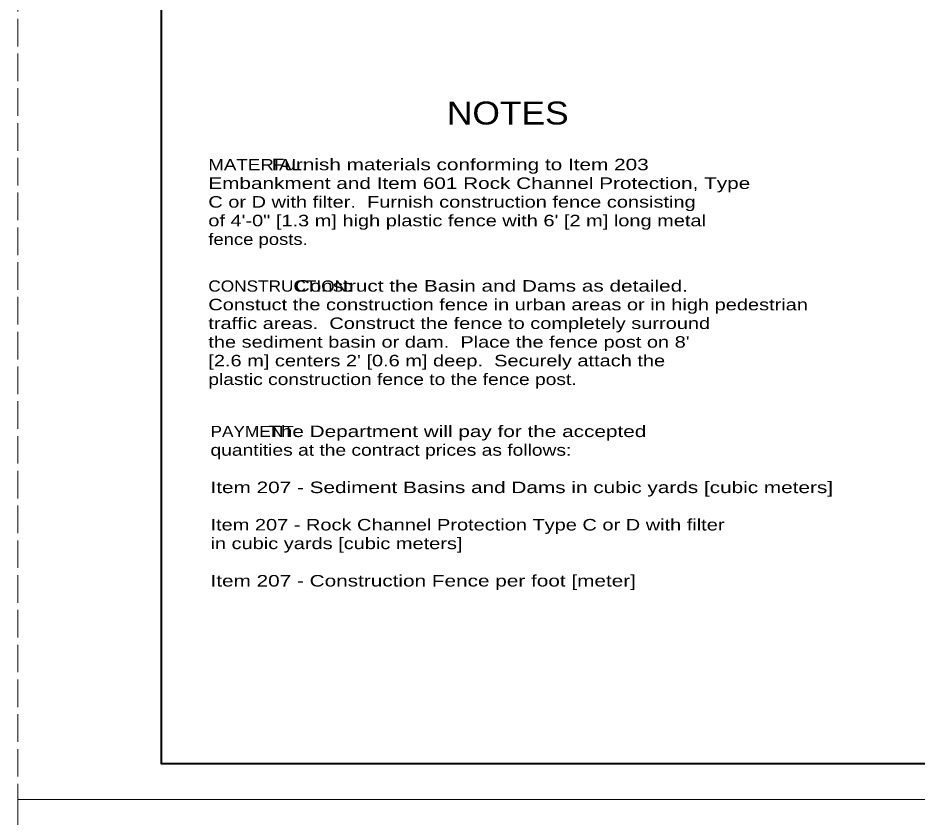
# Model space of a CAD drawing. Extents: x 1043.1 to 1101.1, y 672.4 to 716.4.
# Drawn here: x 1043.14 to 1055.66, y 694.15 to 705.27 of the extents above; entities that cross this region are included whole.
import ezdxf
from ezdxf.enums import TextEntityAlignment as Align

# ---------------------------------------------------------------- set-up
doc = ezdxf.new("R2010")
doc.units = 0
doc.header["$LTSCALE"] = 0.064
doc.linetypes.add('LONG_DASHED', pattern=[7.5, 6, -1.5])
doc.layers.add('1', color=7, linetype='Continuous', lineweight=13)

msp = doc.modelspace()

# ---------------------------------------------------------------- linework, layer by layer
at = {"layer": '1', "linetype": 'LONG_DASHED'}
for points in [[(1043.14425, 694.39508), (1077.14425, 694.39508), (1077.14425, 716.39508), (1043.14425, 716.39508)], [(1043.14425, 672.39508), (1077.14425, 672.39508), (1077.14425, 694.39508), (1043.14425, 694.39508)]]:
    msp.add_lwpolyline(points, close=True, dxfattribs=at)
at = {"layer": '1', "lineweight": 25}
msp.add_lwpolyline([(1076.64425, 694.89508), (1045.14425, 694.89508), (1045.14425, 715.89508)], dxfattribs=at)
at = {"layer": '1', "lineweight": 40}
msp.add_lwpolyline([(1045.14425, 715.89508), (1076.64425, 715.89508), (1076.64425, 694.89508), (1045.14425, 694.89508)], close=True, dxfattribs=at)
msp.add_lwpolyline([(1076.64425, 694.89508), (1045.14425, 694.89508), (1045.14425, 715.89508)], dxfattribs=at)

# ---------------------------------------------------------------- texts
at = {"layer": '1', "width": 1.15}
msp.add_text('NOTES', height=0.32, dxfattribs=at).set_placement((1049.96412, 703.7915), align=Align.CENTER)
at = {"layer": '1'}
for s, height, width, p in [('MATERIAL:', 0.156, 1.25, (1045.7945, 703.15467)), ('           Furnish materials conforming to Item 203', 0.16, 1.35, (1045.7945, 703.15467)), ('Embankment and Item 601 Rock Channel Protection, Type', 0.16, 1.35, (1045.7945, 702.89467)), ('C or D with filter.  Furnish construction fence consisting', 0.16, 1.3, (1045.7945, 702.63467)), ('of 4\'-0" [1.3 m] high plastic fence with 6\' [2 m] long metal', 0.16, 1.3, (1045.7945, 702.37467)), ('fence posts.', 0.16, 1.2, (1045.7945, 702.11467)), ('CONSTRUCTION:', 0.156, 1.15, (1045.7945, 701.46533)), ('               Construct the Basin and Dams as detailed. ', 0.16, 1.35, (1045.7945, 701.46533)), ('Constuct the construction fence in urban areas or in high pedestrian', 0.16, 1.3, (1045.7945, 701.20533)), ('traffic areas.  Construct the fence to completely surround', 0.16, 1.3, (1045.7945, 700.94533)), ("the sediment basin or dam.  Place the fence post on 8'", 0.16, 1.3, (1045.7945, 700.68533)), ("[2.6 m] centers 2' [0.6 m] deep.  Securely attach the", 0.16, 1.3, (1045.7945, 700.42533)), ('plastic construction fence to the fence post.', 0.16, 1.25, (1045.7945, 700.16533)), ('PAYMENT:', 0.156, 1.15, (1045.825, 699.44125)), ('          The Department will pay for the accepted', 0.16, 1.35, (1045.825, 699.44125)), ('quantities at the contract prices as follows:', 0.16, 1.25, (1045.825, 699.18125)), ('Item 207 - Sediment Basins and Dams in cubic yards [cubic meters]', 0.16, 1.35, (1045.825, 698.66125)), ('Item 207 - Rock Channel Protection Type C or D with filter', 0.16, 1.3, (1045.825, 698.14125)), ('in cubic yards [cubic meters]', 0.16, 1.3, (1045.825, 697.88125)), ('Item 207 - Construction Fence per foot [meter]', 0.16, 1.35, (1045.825, 697.36125))]:
    msp.add_text(s, height=height, dxfattribs=dict(at, width=width)).set_placement(p)

doc.saveas('drawing.dxf')
